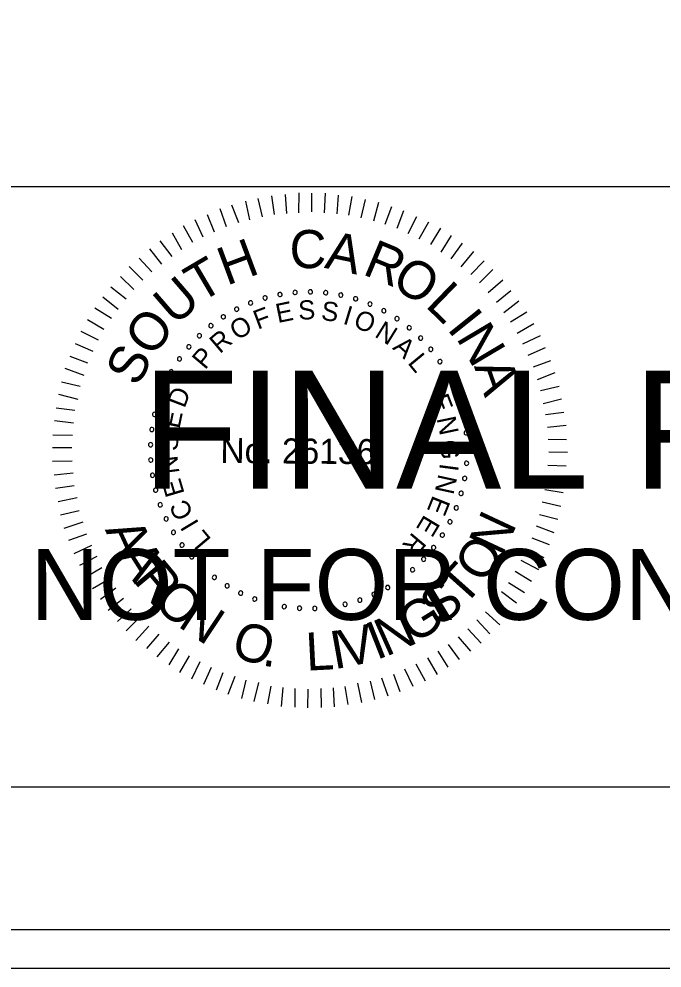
# Model space of a CAD drawing. Extents: x 967 to 1326, y 964 to 1744.
# Drawn here: x 1170.56 to 1189.3, y 1523.72 to 1551.36 of the extents above; entities that cross this region are included whole.
import ezdxf

# ---------------------------------------------------------------- set-up
doc = ezdxf.new("R2010")
doc.units = 0
for name, color, linetype in [('RD_PD_PaveShd', 7, 'Continuous'), ('RD_XS_Base', 7, 'Continuous'), ('RD_XS_CurbBase', 7, 'Continuous'), ('RD_XS_TieSlope', 7, 'Continuous'), ('RD_XS_TX_TOC', 7, 'Continuous')]:
    doc.layers.add(name, color=color, linetype=linetype)

msp = doc.modelspace()

# ---------------------------------------------------------------- linework, layer by layer
at = {"layer": 'RD_PD_PaveShd'}
for p, q in [((996.114, 1546.486), (1323.886, 1546.486)), ((1323.886, 1528.983), (996.114, 1528.983))]:
    msp.add_line(p, q, dxfattribs=at)
at = {"layer": 'RD_XS_CurbBase'}
msp.add_lwpolyline([(967.409, 1523.72), (1326.285, 1523.72), (1326.285, 1743.72), (967.409, 1743.72)], close=True, dxfattribs=at)
at = {"layer": 'RD_XS_TieSlope'}
for p, q in [((1178.01, 1545.663), (1177.93, 1546.209)), ((1178.364, 1545.699), (1178.33, 1546.244)), ((1178.717, 1545.719), (1178.722, 1546.295)), ((1179.093, 1545.739), (1179.098, 1546.292)), ((1179.469, 1545.713), (1179.489, 1546.288)), ((1179.829, 1545.687), (1179.872, 1546.231)), ((1180.174, 1545.646), (1180.271, 1546.19)), ((1176.964, 1545.419), (1176.769, 1545.935)), ((1177.287, 1545.508), (1177.169, 1546.054)), ((1177.657, 1545.597), (1177.53, 1546.128)), ((1180.535, 1545.573), (1180.662, 1546.102)), ((1180.902, 1545.478), (1181.045, 1546.022)), ((1181.231, 1545.384), (1181.428, 1545.896)), ((1176.264, 1545.156), (1176.053, 1545.657)), ((1176.61, 1545.306), (1176.423, 1545.83)), ((1181.584, 1545.265), (1181.78, 1545.786)), ((1175.933, 1545.005), (1175.699, 1545.506)), ((1181.905, 1545.109), (1182.154, 1545.606)), ((1182.226, 1544.953), (1182.506, 1545.45)), ((1175.308, 1544.634), (1175.036, 1545.12)), ((1175.624, 1544.846), (1175.352, 1545.332)), ((1182.562, 1544.789), (1182.85, 1545.27)), ((1175.03, 1544.445), (1174.681, 1544.9)), ((1182.86, 1544.572), (1183.163, 1545.053)), ((1183.158, 1544.378), (1183.484, 1544.828)), ((1174.729, 1544.217), (1174.372, 1544.665)), ((1183.447, 1544.145), (1183.811, 1544.587)), ((1174.435, 1543.997), (1174.062, 1544.399)), ((1183.729, 1543.92), (1184.116, 1544.316)), ((1174.172, 1543.753), (1173.776, 1544.148)), ((1183.98, 1543.672), (1184.368, 1544.061)), ((1173.909, 1543.479), (1173.52, 1543.858)), ((1184.232, 1543.394), (1184.657, 1543.767)), ((1173.684, 1543.197), (1173.242, 1543.546)), ((1184.475, 1543.108), (1184.892, 1543.45)), ((1173.451, 1542.9), (1173.009, 1543.256)), ((1184.687, 1542.807), (1185.128, 1543.156)), ((1173.257, 1542.64), (1172.776, 1542.936)), ((1173.039, 1542.312), (1172.559, 1542.6)), ((1184.885, 1542.544), (1185.355, 1542.832)), ((1185.081, 1542.213), (1185.56, 1542.493)), ((1172.883, 1542.006), (1172.379, 1542.256)), ((1185.24, 1541.904), (1185.756, 1542.145)), ((1172.727, 1541.677), (1172.215, 1541.904)), ((1185.399, 1541.573), (1185.907, 1541.791)), ((1172.571, 1541.333), (1172.051, 1541.53)), ((1185.549, 1541.226), (1186.057, 1541.414)), ((1172.461, 1540.974), (1171.91, 1541.178)), ((1185.669, 1540.865), (1186.185, 1541.06)), ((1172.351, 1540.652), (1171.807, 1540.787)), ((1185.759, 1540.541), (1186.297, 1540.667)), ((1172.286, 1540.276), (1171.727, 1540.419)), ((1185.832, 1540.165), (1186.371, 1540.298)), ((1172.191, 1539.955), (1171.647, 1540.029)), ((1185.906, 1539.842), (1186.436, 1539.906)), ((1172.15, 1539.587), (1171.598, 1539.653)), ((1185.964, 1539.473), (1186.51, 1539.53)), ((1172.124, 1539.234), (1171.548, 1539.239)), ((1185.977, 1539.12), (1186.514, 1539.115)), ((1172.105, 1538.866), (1171.545, 1538.871)), ((1185.997, 1538.751), (1186.542, 1538.747)), ((1172.118, 1538.482), (1171.542, 1538.471)), ((1185.971, 1538.368), (1186.508, 1538.348)), ((1172.138, 1538.136), (1171.585, 1538.072)), ((1185.952, 1538.022), (1186.497, 1537.949)), ((1172.173, 1537.768), (1171.627, 1537.688)), ((1185.888, 1537.655), (1186.417, 1537.566)), ((1172.262, 1537.414), (1171.701, 1537.296)), ((1185.808, 1537.302), (1186.345, 1537.175)), ((1172.321, 1537.037), (1171.774, 1536.911)), ((1185.729, 1536.926), (1186.265, 1536.792)), ((1172.425, 1536.707), (1171.871, 1536.519)), ((1185.634, 1536.597), (1186.146, 1536.401)), ((1172.53, 1536.36), (1172.007, 1536.173)), ((1185.508, 1536.253), (1186.013, 1536.057)), ((1172.681, 1536.029), (1172.165, 1535.788)), ((1172.831, 1535.705), (1172.323, 1535.441)), ((1185.352, 1535.924), (1185.857, 1535.675)), ((1185.188, 1535.603), (1185.7, 1535.33)), ((1172.982, 1535.374), (1172.497, 1535.094)), ((1185.024, 1535.274), (1185.498, 1534.987)), ((1173.194, 1535.042), (1172.709, 1534.762)), ((1184.822, 1534.946), (1185.288, 1534.658)), ((1173.384, 1534.78), (1172.936, 1534.453)), ((1184.62, 1534.687), (1185.055, 1534.353)), ((1173.612, 1534.478), (1173.164, 1534.129)), ((1184.403, 1534.389), (1184.814, 1534.033)), ((1173.832, 1534.177), (1173.437, 1533.812)), ((1184.155, 1534.092), (1184.574, 1533.72)), ((1174.091, 1533.945), (1173.689, 1533.541)), ((1183.899, 1533.864), (1184.28, 1533.454)), ((1174.35, 1533.674), (1173.97, 1533.263)), ((1183.644, 1533.597), (1184.024, 1533.18)), ((1174.64, 1533.442), (1174.275, 1533.022)), ((1174.937, 1533.209), (1174.58, 1532.782)), ((1183.358, 1533.37), (1183.715, 1532.944)), ((1175.212, 1533.014), (1174.932, 1532.549)), ((1182.764, 1532.952), (1183.059, 1532.482)), ((1183.065, 1533.141), (1183.384, 1532.709)), ((1175.525, 1532.812), (1175.245, 1532.331)), ((1175.83, 1532.633), (1175.588, 1532.136)), ((1182.463, 1532.755), (1182.743, 1532.269)), ((1176.159, 1532.477), (1175.94, 1531.98)), ((1181.8, 1532.431), (1182.041, 1531.93)), ((1182.124, 1532.581), (1182.396, 1532.08)), ((1176.503, 1532.321), (1176.307, 1531.816)), ((1176.855, 1532.211), (1176.651, 1531.69)), ((1177.177, 1532.1), (1177.05, 1531.572)), ((1181.122, 1532.175), (1181.31, 1531.652)), ((1181.476, 1532.28), (1181.664, 1531.771)), ((1177.545, 1532.036), (1177.409, 1531.484)), ((1177.897, 1531.933), (1177.808, 1531.412)), ((1178.25, 1531.892), (1178.207, 1531.34)), ((1178.603, 1531.866), (1178.598, 1531.313)), ((1178.978, 1531.84), (1178.974, 1531.295)), ((1179.355, 1531.86), (1179.365, 1531.307)), ((1179.715, 1531.88), (1179.749, 1531.327)), ((1180.061, 1531.915), (1180.149, 1531.393)), ((1180.423, 1532.012), (1180.541, 1531.458)), ((1180.791, 1532.07), (1180.926, 1531.54))]:
    msp.add_line(p, q, dxfattribs=at)
for centre, start, end in [((1178.609, 1543.397), 5.0653, 185.0653), ((1179.055, 1543.414), 359.5268, 179.5268), ((1179.055, 1543.414), 179.5268, 359.5268), ((1179.5, 1543.388), 353.9884, 173.9884), ((1177.312, 1543.091), 21.6807, 201.6807), ((1177.734, 1543.235), 16.1422, 196.1422), ((1177.734, 1543.235), 196.1422, 16.1422), ((1178.168, 1543.337), 10.6038, 190.6038), ((1178.168, 1543.337), 190.6038, 10.6038), ((1178.609, 1543.397), 185.0653, 5.0653), ((1179.5, 1543.388), 173.9884, 353.9884), ((1179.94, 1543.319), 168.4499, 348.4499), ((1179.94, 1543.319), 348.4499, 168.4499), ((1180.372, 1543.208), 162.9114, 342.9114), ((1180.372, 1543.208), 342.9114, 162.9114), ((1176.906, 1542.908), 27.2191, 207.2191), ((1176.906, 1542.908), 207.2191, 27.2191), ((1177.312, 1543.091), 201.6807, 21.6807), ((1180.79, 1543.056), 157.373, 337.373), ((1180.79, 1543.056), 337.373, 157.373), ((1181.193, 1542.864), 151.8345, 331.8345), ((1181.193, 1542.864), 331.8345, 151.8345), ((1176.52, 1542.686), 32.7576, 212.7576), ((1176.52, 1542.686), 212.7576, 32.7576), ((1181.574, 1542.634), 146.2961, 326.2961), ((1181.574, 1542.634), 326.2961, 146.2961), ((1176.156, 1542.428), 38.2961, 218.2961), ((1176.156, 1542.428), 218.2961, 38.2961), ((1181.932, 1542.368), 140.7576, 320.7576), ((1181.932, 1542.368), 320.7576, 140.7576), ((1175.82, 1542.135), 43.8345, 223.8345), ((1175.82, 1542.135), 223.8345, 43.8345), ((1182.263, 1542.069), 135.2191, 315.2191), ((1182.263, 1542.069), 315.2191, 135.2191), ((1175.513, 1541.812), 49.373, 229.373), ((1175.513, 1541.812), 229.373, 49.373), ((1182.563, 1541.74), 129.6807, 309.6807), ((1182.563, 1541.74), 309.6807, 129.6807), ((1175.239, 1541.461), 54.9114, 234.9114), ((1175.239, 1541.461), 234.9114, 54.9114), ((1182.83, 1541.383), 124.1422, 304.1422), ((1182.83, 1541.383), 304.1422, 124.1422), ((1175, 1541.085), 60.4499, 240.4499), ((1175, 1541.085), 240.4499, 60.4499), ((1183.061, 1541.002), 118.6038, 298.6038), ((1183.061, 1541.002), 298.6038, 118.6038), ((1174.798, 1540.687), 65.9884, 245.9884), ((1174.798, 1540.687), 245.9884, 65.9884), ((1183.255, 1540.601), 113.0653, 293.0653), ((1183.255, 1540.601), 293.0653, 113.0653), ((1174.636, 1540.272), 71.5268, 251.5268), ((1174.636, 1540.272), 251.5268, 71.5268), ((1183.408, 1540.182), 107.5268, 287.5268), ((1183.408, 1540.182), 287.5268, 107.5268), ((1174.514, 1539.843), 77.0653, 257.0653), ((1174.514, 1539.843), 257.0653, 77.0653), ((1183.521, 1539.751), 101.9884, 281.9884), ((1183.521, 1539.751), 281.9884, 101.9884), ((1174.435, 1539.405), 82.6038, 262.6038), ((1174.435, 1539.405), 262.6038, 82.6038), ((1183.592, 1539.311), 96.4499, 276.4499), ((1183.592, 1539.311), 276.4499, 96.4499), ((1174.398, 1538.961), 88.1422, 268.1422), ((1174.398, 1538.961), 268.1422, 88.1422), ((1183.619, 1538.866), 90.9114, 270.9114), ((1183.619, 1538.866), 270.9114, 90.9114), ((1174.404, 1538.515), 93.6807, 273.6807), ((1174.404, 1538.515), 273.6807, 93.6807), ((1183.604, 1538.421), 85.373, 265.373), ((1183.604, 1538.421), 265.373, 85.373), ((1174.453, 1538.072), 99.2191, 279.2191), ((1174.453, 1538.072), 279.2191, 99.2191), ((1183.546, 1537.979), 79.8345, 259.8345), ((1183.546, 1537.979), 259.8345, 79.8345), ((1174.545, 1537.636), 104.7576, 284.7576), ((1174.545, 1537.636), 284.7576, 104.7576), ((1183.445, 1537.545), 74.2961, 254.2961), ((1183.445, 1537.545), 254.2961, 74.2961), ((1174.678, 1537.211), 110.2961, 290.2961), ((1174.678, 1537.211), 290.2961, 110.2961), ((1183.303, 1537.122), 68.7576, 248.7576), ((1183.303, 1537.122), 248.7576, 68.7576), ((1174.852, 1536.8), 115.8345, 295.8345), ((1174.852, 1536.8), 295.8345, 115.8345), ((1183.121, 1536.716), 63.2191, 243.2191), ((1183.121, 1536.716), 243.2191, 63.2191), ((1175.065, 1536.409), 121.373, 301.373), ((1175.065, 1536.409), 301.373, 121.373), ((1182.9, 1536.328), 57.6807, 237.6807), ((1182.9, 1536.328), 237.6807, 57.6807), ((1175.314, 1536.039), 126.9114, 306.9114), ((1175.314, 1536.039), 306.9114, 126.9114), ((1182.643, 1535.964), 52.1422, 232.1422), ((1182.643, 1535.964), 232.1422, 52.1422), ((1175.598, 1535.696), 132.4499, 312.4499), ((1175.598, 1535.696), 312.4499, 132.4499), ((1182.353, 1535.627), 46.6038, 226.6038), ((1182.353, 1535.627), 226.6038, 46.6038), ((1175.914, 1535.381), 137.9884, 317.9884), ((1175.914, 1535.381), 317.9884, 137.9884), ((1176.258, 1535.099), 143.5268, 323.5268), ((1176.258, 1535.099), 323.5268, 143.5268), ((1182.03, 1535.319), 41.0653, 221.0653), ((1182.03, 1535.319), 221.0653, 41.0653), ((1176.629, 1534.851), 149.0653, 329.0653), ((1176.629, 1534.851), 329.0653, 149.0653), ((1181.305, 1534.803), 29.9884, 209.9884), ((1181.68, 1535.043), 35.5268, 215.5268), ((1181.68, 1535.043), 215.5268, 35.5268), ((1177.021, 1534.639), 154.6038, 334.6038), ((1177.021, 1534.639), 334.6038, 154.6038), ((1180.908, 1534.6), 24.4499, 204.4499), ((1180.908, 1534.6), 204.4499, 24.4499), ((1181.305, 1534.803), 209.9884, 29.9884), ((1177.432, 1534.467), 160.1422, 340.1422), ((1177.432, 1534.467), 340.1422, 160.1422), ((1177.858, 1534.335), 165.6807, 345.6807), ((1177.858, 1534.335), 345.6807, 165.6807), ((1178.294, 1534.245), 351.2191, 171.2191), ((1179.627, 1534.232), 7.8345, 187.8345), ((1180.065, 1534.313), 13.373, 193.373), ((1180.065, 1534.313), 193.373, 13.373), ((1180.494, 1534.436), 18.9114, 198.9114), ((1180.494, 1534.436), 198.9114, 18.9114), ((1178.294, 1534.245), 171.2191, 351.2191), ((1178.737, 1534.198), 356.7576, 176.7576), ((1178.737, 1534.198), 176.7576, 356.7576), ((1179.183, 1534.193), 2.2961, 182.2961), ((1179.183, 1534.193), 182.2961, 2.2961), ((1179.627, 1534.232), 187.8345, 7.8345)]:
    msp.add_arc(centre, 0.0627, start, end, dxfattribs=at)
at = {"layer": 'RD_XS_TX_TOC'}
for points in [[(967.409, 1523.72), (1326.285, 1523.72), (1326.285, 1743.72), (967.409, 1743.72)], [(988.525, 1524.84), (1326.285, 1524.84), (1326.285, 1742.6), (988.525, 1742.6)]]:
    msp.add_lwpolyline(points, close=True, dxfattribs=at)

# ---------------------------------------------------------------- texts
at = {"layer": 'RD_XS_Base'}
for s, height, p in [('FINAL PLANS', 3.4375, (1174.145, 1537.685)), ('NOT FOR CONSTRUCTION', 2.0625, (1170.901, 1533.86))]:
    msp.add_text(s, height=height, dxfattribs=at).set_placement(p)
at = {"layer": 'RD_XS_TieSlope'}
for s, height, rotation, p in [('C', 1.11, 359.5482, (1178.442, 1544.108)), ('A', 1.11, 348.1981, (1179.439, 1544.115)), ('H', 1.11, 20.3637, (1176.614, 1543.587)), ('R', 1.11, 337.4344, (1180.541, 1543.937)), ('T', 1.11, 30.4992, (1175.828, 1543.072)), ('O', 1.108, 326.5869, (1181.366, 1543.609)), ('U', 1.11, 40.8022, (1175.102, 1542.403)), ('L', 1.11, 315.9488, (1182.373, 1543.003)), ('E', 0.557, 11.4103, (1178.103, 1542.503)), ('S', 0.557, 2.208, (1178.709, 1542.601)), ('S', 0.557, 352.6608, (1179.346, 1542.599)), ('F', 0.557, 20.6127, (1177.52, 1542.309)), ('I', 0.557, 343.1136, (1179.975, 1542.491)), ('O', 0.557, 338.4392, (1180.274, 1542.401)), ('I', 1.11, 308.6613, (1183.011, 1542.338)), ('O', 1.11, 52.0267, (1174.435, 1541.474)), ('O', 0.557, 30.8477, (1176.917, 1541.987)), ('N', 0.557, 328.2042, (1180.896, 1542.12)), ('N', 1.11, 300.7037, (1183.285, 1542.075)), ('R', 0.557, 40.3949, (1176.415, 1541.594)), ('A', 0.557, 318.657, (1181.424, 1541.762)), ('S', 1.108, 63.2511, (1174.029, 1540.619)), ('P', 0.557, 49.9421, (1175.985, 1541.124)), ('L', 0.557, 309.4546, (1181.869, 1541.339)), ('A', 1.11, 289.4792, (1183.814, 1541.243)), ('D', 0.557, 69.0364, (1175.386, 1540.003)), ('E', 0.557, 291.049, (1182.53, 1540.307)), ('E', 0.557, 78.2388, (1175.238, 1539.407)), ('N', 0.557, 281.8466, (1182.728, 1539.726)), ('S', 0.557, 87.786, (1175.187, 1538.772)), ('No. 26136', 0.7311, 359.5268, (1176.429, 1538.43)), ('G', 0.557, 272.2995, (1182.833, 1539.097)), ('N', 0.557, 97.3332, (1175.242, 1538.137)), ('I', 0.557, 262.4084, (1182.83, 1538.437)), ('E', 0.557, 106.5355, (1175.394, 1537.541)), ('N', 0.557, 257.7339, (1182.789, 1538.127)), ('C', 0.557, 116.4266, (1175.661, 1536.938)), ('E', 0.557, 248.1867, (1182.628, 1537.511)), ('I', 0.557, 121.1011, (1175.823, 1536.67)), ('E', 0.557, 238.9844, (1182.378, 1536.949)), ('N', 1.105, 64.8922, (1184.632, 1535.684)), ('A', 1.105, 294.7297, (1173.062, 1536.486)), ('L', 0.557, 129.9595, (1176.187, 1536.204)), ('R', 0.557, 229.782, (1182.041, 1536.435)), ('O', 1.105, 56.2059, (1184.102, 1534.874)), ('A', 1.105, 302.2892, (1173.414, 1535.72)), ('R', 1.105, 309.8487, (1173.865, 1535.007)), ('T', 1.105, 48.2685, (1183.515, 1534.211)), ('O', 1.105, 317.7861, (1174.434, 1534.33)), ('S', 1.105, 40.3311, (1182.842, 1533.636)), ('N', 1.105, 326.4725, (1175.158, 1533.686)), ('G', 1.105, 32.0198, (1182.059, 1533.14)), ('N', 1.105, 24.0824, (1181.252, 1532.776)), ('O', 1.105, 342.3472, (1176.697, 1532.82)), ('V', 1.105, 12.7741, (1180.033, 1532.457)), ('I', 1.105, 21.4605, (1180.976, 1532.681)), ('L', 1.105, 2.9677, (1178.943, 1532.379)), ('I', 1.105, 10.1523, (1179.743, 1532.418)), ('.', 1.105, 351.0336, (1177.623, 1532.536))]:
    msp.add_text(s, height=height, rotation=rotation, dxfattribs=at).set_placement(p)

doc.saveas('drawing.dxf')
